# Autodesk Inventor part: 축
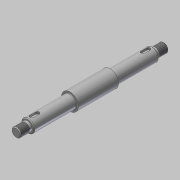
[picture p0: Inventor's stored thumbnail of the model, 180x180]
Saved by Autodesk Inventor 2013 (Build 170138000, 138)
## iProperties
Created: 2018-11
Part Number: 축
Material: 강철, 연강
Document SubType Name: Modeling
Designer: mduedu
Density: 1 g/cm^3
Author: mduedu
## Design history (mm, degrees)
sketch "스케치1"
  geometry: L1 (-26, 0)-(26, 0); L2 (26, 0)-(26, 11); L3 (26, 11)-(-26, 11); L4 (-26, 11)-(-26, 0); L5 (-26, 0)-(-81, 0); L6 (-81, 0)-(-81, 8.5); L7 (-81, 8.5)-(-26, 8.5); L8 (-26, 8.5)-(-26, 0); L9 (-81, 0)-(-96, 0); L10 (-96, 0)-(-96, 6); L11 (-96, 6)-(-81, 6); L12 (-81, 6)-(-81, 0); L13 (0, 0)-(0, 11); L14 (26, 0)-(81, 0); L15 (81, 0)-(81, 8.5); L16 (81, 8.5)-(26, 8.5); L17 (26, 8.5)-(26, 0); L18 (81, 0)-(96, 0); L19 (96, 0)-(96, 6); L20 (96, 6)-(81, 6); L21 (81, 6)-(81, 0); 1 further point
  constraints: 42 end point, 6 parallel, 6 symmetric about line, 3 horizontal, 3 perpendicular, 2 midpoint, 1 coincident
  dimensions: "d0" = 22 diameter of L3 L1; "d2" = 17 diameter of L7 L5; "d3" = 12 diameter of L11 L9; "d4" = 52 distance of L2.end L3.end; "d5" = 55 distance of L6.end L7.end; "d6" = 192 distance between parallel lines of L19 L10
revolve "회전1" sketch "스케치1" stored, may be unused: angle "d7" = 90 deg
fillet "모깎기1" dims "d8" = 0.6
node "작업 평면1"
sketch "스케치2" dims "d11" = 12
  geometry: L1 (15, 2.5)-(22, 2.5); L2 (22, 2.5)-(22, -2.5); L3 (22, -2.5)-(15, -2.5); L4 (15, -2.5)-(15, 2.5); L5 (27.5, 8.5)-(27.5, -8.5) reference; 3 further points
  constraints: 8 end point, 2 midpoint, 2 parallel, 2 vertical alignment, 1 horizontal, 1 horizontal alignment, 1 perpendicular, 4 other
  dimensions: "d9" = 3 dimension on L5; "d10" = 5 distance between parallel lines of L3 L1
extrude "돌출1" cut sketch "스케치2" distance "d12" = 3; taper "d13" = 0 deg
chamfer "모따기1" distance "d14" = 1; stored, may be unused: second distance "d15" = 2, angle "d16" = 45 deg
feature "스레드1" dims "d17" = 12, "d18" = 0
feature "스레드2" dims "d19" = 12, "d20" = 0
chamfer "모따기2" distance "d21" = 1; stored, may be unused: second distance "d22" = 2, angle "d23" = 45 deg
node "솔리드1"
mirror "대칭1"
